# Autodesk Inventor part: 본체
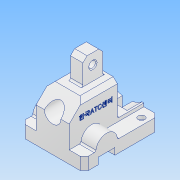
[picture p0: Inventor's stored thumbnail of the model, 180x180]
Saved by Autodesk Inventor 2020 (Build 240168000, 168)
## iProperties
Created: 2022-08
Part Number: 본체
Material: 알루미늄 6061
Document SubType Name: Modeling
Designer: user
Density: 2.7 g/cm^3
Appearance: 알루미늄 - 평지
Mass: 510.274 g
Surface Area: 332.556 cm^2
Volume: 188.99 cm^3
Author: user
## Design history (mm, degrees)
sketch "스케치1"
  geometry: L1 (20, -22.5)-(-20, -22.5); L2 (-20, -22.5)-(-20, 22.5); L3 (-20, 22.5)-(20, 22.5); L4 (20, 22.5)-(20, -22.5); L5 (20, -22.5)-(-20, 22.5); L6 (-20, -22.5)-(20, 22.5); 1 further point
  constraints: 12 end point, 2 midpoint, 2 parallel, 1 horizontal, 1 perpendicular
  dimensions: "d0" = 45 distance of L1.end L2.end; "d1" = 40 distance of L2.end L3.end
extrude "돌출1" new body sketch "스케치1" distance "d2" = 58; taper "d3" = 0 deg
chamfer "모따기1" distance "d4" = 18; stored, may be unused: second distance "d5" = 2, angle "d6" = 45 deg
chamfer "모따기2" distance "d7" = 5; stored, may be unused: second distance "d8" = 2, angle "d9" = 45 deg
sketch "스케치2"
  geometry: L1 (20, -22.5)-(-20, -22.5) reference; L2 (-15, 22.5)-(15, 22.5) reference; C1 r 10 at (0, 4.5); 1 further point
  constraints: 1 centre point, 1 midpoint, 1 vertical alignment
  dimensions: "d10" = 20 diameter of C1; "d57" = 27 distance from line of L1 C1.centre
extrude "돌출2" cut sketch "스케치2" extent not by distance; stored distance "d11" = 0; taper "d12" = 0 deg
sketch "스케치3"
  geometry: L1 (-20, -22.5)-(20, -22.5) reference; L2 (15, 22.5)-(-15, 22.5) reference; C1 r 14.5 at (0, 4.5); 1 further point
  constraints: 1 centre point, 1 midpoint, 1 vertical alignment
  dimensions: "d13" = 29 diameter of C1; "d58" = 27 distance from line of L1 C1.centre
extrude "돌출3" cut sketch "스케치3" distance "d14" = 7; taper "d15" = 0 deg
sketch "스케치4"
  geometry: L1 (7.5, 11)-(22.5, 11); L2 (22.5, 11)-(22.5, 35); L3 (22.5, 35)-(7.5, 35); L4 (7.5, 35)-(7.5, 11); L5 (0, 40)-(30, 40) reference; 2 further points
  constraints: 8 end point, 2 parallel, 1 horizontal, 1 midpoint, 1 perpendicular, 1 vertical alignment
  dimensions: "d16" = 24 distance of L3.end L1.start; "d17" = 5 distance between parallel lines of L5 L3; "d18" = 15 distance of L1.start L1.end
extrude "돌출4" join sketch "스케치4" distance "d19" = 30; taper "d20" = 0 deg
chamfer "모따기3" distance "d21" = 5; stored, may be unused: second distance "d22" = 2, angle "d23" = 45 deg
sketch "스케치5"
  geometry: L1 (24, 0)-(24, 25) reference; L2 (22, -3.5)-(22, -32.5) reference; L3 (29, -3.5)-(29, -32.5) reference; L4 (29, -45)-(29, -5) reference; L5 (29, -18)-(22, -18); L6 (22, -28)-(22, -8) reference; L7 (19, 30)-(5, 30) reference; C1 r 4 at (12, 17); 2 further points
  constraints: 2 end point, 2 midpoint, 1 centre point, 1 horizontal, 1 point on line, 1 vertical alignment
  dimensions: "d60" = 8 diameter of C1; "d61" = 35 vertical distance of L5.start C1.centre
extrude "돌출5" cut sketch "스케치5" extent not by distance; stored distance "d27" = 0; taper "d28" = 0 deg
sketch "스케치6"
  geometry: L1 (0, 0)-(0, 27) reference; L2 (0, 0)-(90, 0); L3 (90, 0)-(90, -15); L4 (90, -15)-(0, -15); L5 (0, -15)-(0, 0); L6 (0, 0)-(58, 0) reference; L7 (17, -15)-(37, -15); L8 (37, -15)-(37, -7); L9 (37, -7)-(17, -7); L10 (17, -7)-(17, -15); A1 r 13 centre (27, 0) between (40, 0) and (14, 0); 5 further points
  constraints: 16 end point, 4 parallel, 4 point on line, 2 horizontal, 2 perpendicular, 2 point on circle, 1 centre point, 1 midpoint, 1 vertical alignment
  dimensions: "d37" = 90 distance of L3.end L4.end; "d38" = 15 distance of L4.end L1.start; "d39" = 26 diameter of A1; "d40" = 27 distance from line of A1.centre L5; "d41" = 8 distance between parallel lines of L4 L9; "d42" = 20 distance of L8.end L9.end
extrude "돌출6" join sketch "스케치6" distance "d43" = 18; taper "d44" = 0 deg
sketch "스케치7"
  geometry: L1 (0, 0)-(-18, 0) reference; L2 (40, 15)-(40, 0) reference; L3 (0, 0)-(40, 0); L4 (40, 0)-(40, 15); L5 (40, 15)-(0, 15); L6 (0, 15)-(0, 0); 2 further points
  constraints: 8 end point, 2 parallel, 1 horizontal, 1 perpendicular
extrude "돌출7" join sketch "스케치7" distance "d45" = 90; taper "d46" = 0 deg
sketch "스케치8"
  geometry: L1 (-22.5, -40)-(-22.5, -58) reference; L2 (-22.5, -58)-(-18.5, -58); L3 (-18.5, -58)-(-18.5, -90); L4 (-18.5, -90)-(-22.5, -90); L5 (-22.5, -90)-(-22.5, -58); L6 (-37.5, -37)-(-37.5, -90) reference; 2 further points
  constraints: 8 end point, 2 parallel, 1 coincident, 1 horizontal, 1 perpendicular
  dimensions: "d47" = 19 distance between parallel lines of L6 L3
extrude "돌출8" join sketch "스케치8" stored distance "d48" = 40; taper "d49" = 0 deg
sketch "스케치9"
  geometry: C1 r 29 at (38, 27); C2 r 14.5 at (38, 27) reference
  constraints: 1 centre point, 1 coincident
  dimensions: "d84" = 58 diameter of C1
extrude "돌출9" cut sketch "스케치9" distance "d51" = 18; taper "d52" = 0 deg
sketch "스케치10"
  geometry: L1 (76, -15)-(0, -15) reference; L2 (32, -15)-(44, -15); L3 (44, -15)-(44, 4); L4 (44, 4)-(32, 4); L5 (32, 4)-(32, -15); 3 further points
  constraints: 8 end point, 2 parallel, 1 horizontal, 1 midpoint, 1 perpendicular, 1 point on line, 1 vertical alignment
  dimensions: "d53" = 12 distance of L3.end L4.end; "d54" = 19 distance of L4.end L2.start
extrude "돌출10" cut sketch "스케치10" distance "d55" = 18; taper "d56" = 0 deg
sketch "스케치11"
  geometry: L1 (-14, 50)-(18, 50) reference; 3 further points
  constraints: 1 horizontal alignment
  dimensions: "d62" = 60 distance of point (10, 37) point (-50, 37); "d63" = 30 horizontal distance of point (-20, -40) point (-50, 37); "d64" = 13 distance from line of L1 point (10, 37)
hole "구멍1" sketch "스케치11" at (-50, 37), (10, 37) diameter "d65" = 4.5; stored, may be unused: countersink angle "d69" = 90 deg, drill point angle "d71" = 0 deg; dims "d66" = 10, "d67" = 8, "d68" = 4.4, "d70" = 12
chamfer "모따기4" distance "d72" = 5; stored, may be unused: second distance "d73" = 2, angle "d74" = 45 deg
fillet "모깎기1" dims "d75" = 2
node "작업 평면1"
sketch "스케치12"
  geometry: L1 (45, 5)-(5, 5) reference; L2 (45, 0)-(45, -34) reference; 2 further points
  constraints: 1 other
  dimensions: "d77" = 18 distance from line of point (19, -13) L1; "d78" = 26 distance from line of L2 point (19, -13)
feature "엠보싱1" sketch "스케치12" dims "d0" = 45, "d1" = 40, "d79" = 0.5, "d80" = 0
chamfer "모따기5" distance "d81" = 1; stored, may be unused: second distance "d82" = 2, angle "d83" = 45 deg
sketch "스케치13"
  geometry: L1 (-20, 8)-(0, 8) reference; L2 (0, 0)-(48, 0) reference; L3 (-20, 8)-(0, 8); L4 (0, 8)-(0, 0); L5 (0, 0)-(-20, 0); L6 (-20, 0)-(-20, 8); 2 further points
  constraints: 8 end point, 2 parallel, 1 horizontal, 1 perpendicular
extrude "돌출11" cut sketch "스케치13" extent not by distance; stored distance "d85" = 18; taper "d86" = 0 deg
node "솔리드1"
mirror "미러1"
node "투영된 루프1"
feature "A9D066F2-1C7D-4E18-AEED-F7BC21143FA4" dims "d65" = 4.5, "d66" = 10, "d67" = 8, "d68" = 4.4, "d69" = 90 deg, "d70" = 12, "d71" = 0
other parameters: "d32" = 8, "d76" = 22.75
